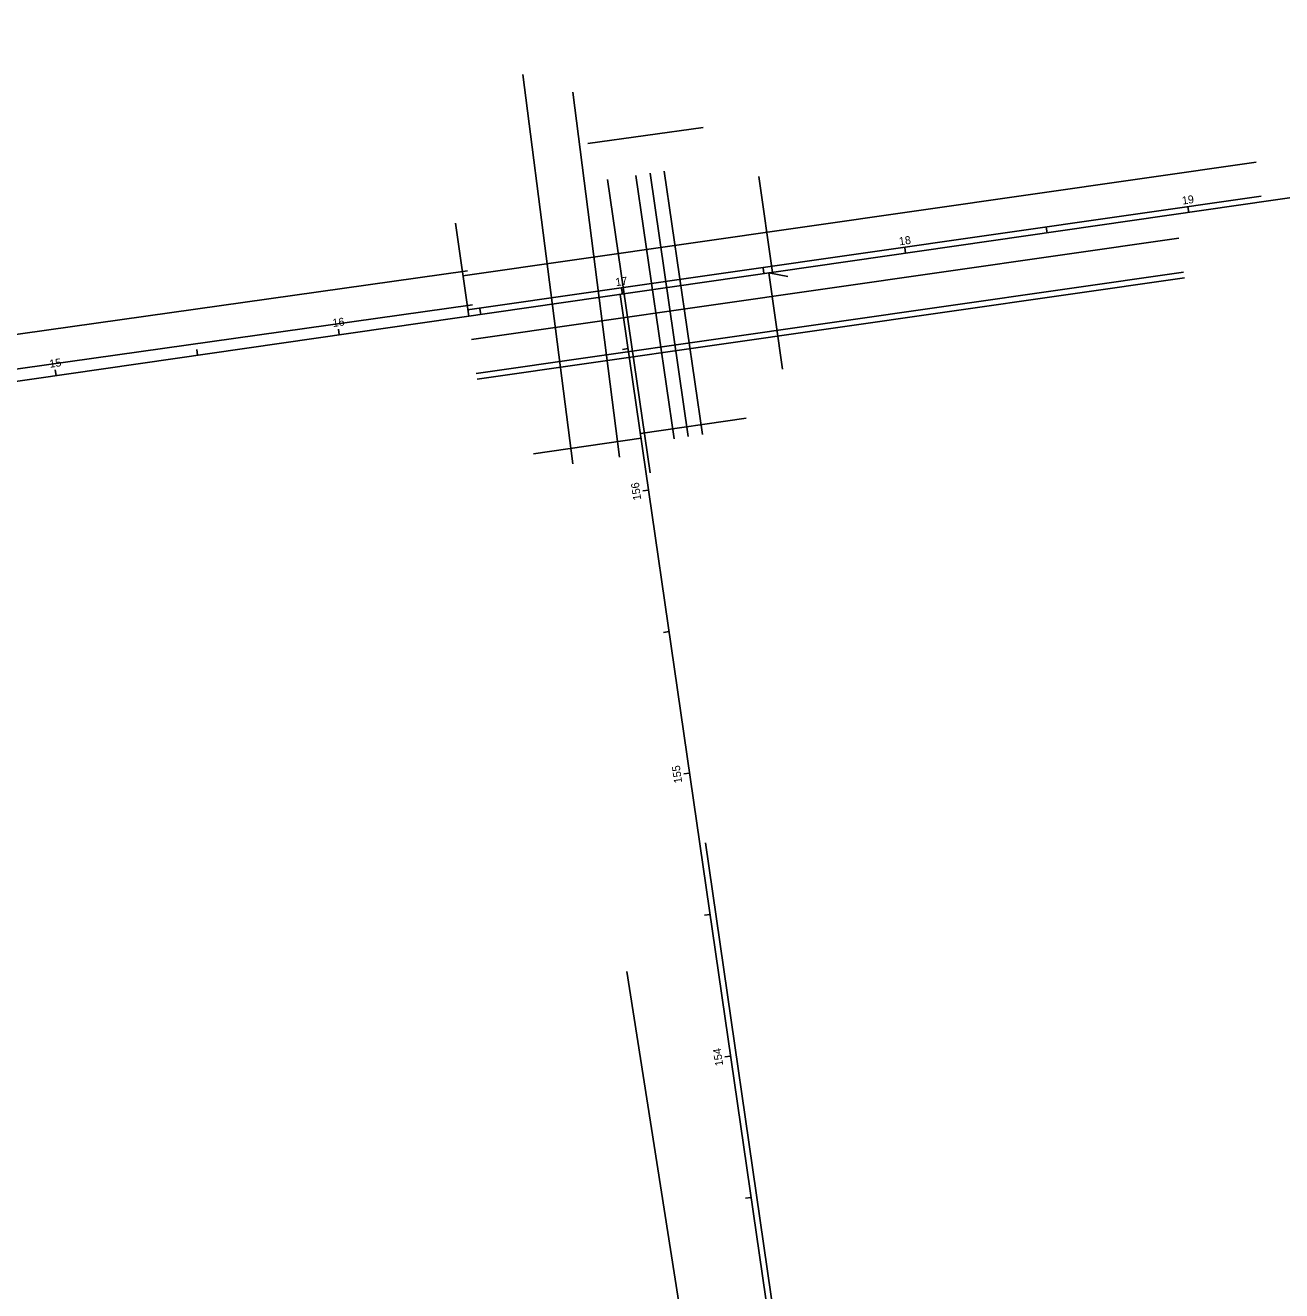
# Model space of a CAD drawing. Extents: x 1827063 to 1831280, y 711192 to 712800.
# Drawn here: x 1828341.4 to 1828780.5, y 712025.4 to 712468 of the extents above; entities that cross this region are included whole.
import ezdxf

# ---------------------------------------------------------------- set-up
doc = ezdxf.new("R2010")
doc.units = 0
for name, color, linetype in [('DR_P_Storm_Sewer', 7, 'Continuous'), ('PV_P_Walk', 7, 'Continuous'), ('UT_X_FO', 7, 'Continuous')]:
    doc.layers.add(name, color=color, linetype=linetype)

msp = doc.modelspace()

# ---------------------------------------------------------------- linework, layer by layer
at = {"layer": 'DR_P_Storm_Sewer'}
for p, q in [((1827917.05, 712282.69), (1829201.8, 712467.95)), ((1828748.02, 712402.52), (1828747.73, 712404.5)), ((1828698.53, 712395.38), (1828698.24, 712397.36)), ((1828649.04, 712388.24), (1828648.75, 712390.22)), ((1828599.55, 712381.11), (1828599.27, 712383.09)), ((1828577.13, 712181.7), (1828549.31, 712373.86)), ((1828550.06, 712373.97), (1828549.78, 712375.95)), ((1828500.58, 712366.84), (1828500.29, 712368.82)), ((1828451.09, 712359.7), (1828450.8, 712361.68)), ((1828401.6, 712352.56), (1828401.31, 712354.54)), ((1828552.06, 712354.9), (1828550.08, 712354.61)), ((1828352.11, 712345.43), (1828351.83, 712347.41)), ((1828559.22, 712305.41), (1828557.24, 712305.13)), ((1828566.39, 712255.93), (1828564.41, 712255.64)), ((1828573.55, 712206.45), (1828571.57, 712206.16)), ((1828611.13, 711946.89), (1828577.13, 712181.7)), ((1828580.71, 712156.96), (1828578.73, 712156.68)), ((1828587.88, 712107.48), (1828585.9, 712107.19)), ((1828595.04, 712057.99), (1828593.06, 712057.71))]:
    msp.add_line(p, q, dxfattribs=at)
at = {"layer": 'PV_P_Walk'}
for p, q in [((1828515.27, 712450.72), (1828532.73, 712314.63)), ((1828549.07, 712316.94), (1828532.69, 712444.62)), ((1828578.25, 712432.26), (1828537.95, 712426.67)), ((1828494.26, 712380.3), (1828771.63, 712420.12)), ((1828559.76, 712311.48), (1828544.9, 712413.98)), ((1828568.14, 712323.37), (1828554.79, 712415.48)), ((1828573.09, 712324.09), (1828559.73, 712416.2)), ((1828578.03, 712324.8), (1828564.68, 712416.92)), ((1828597.71, 712415.06), (1828602.54, 712381.54)), ((1828495.91, 712368.42), (1828773.33, 712408.24)), ((1828491.7, 712398.78), (1828496.39, 712366.23)), ((1828497.35, 712358.01), (1828744.54, 712393.5)), ((1828004.58, 712312.75), (1828495.96, 712382.05)), ((1828499, 712346.13), (1828746.25, 712381.62)), ((1828499.28, 712344.15), (1828746.53, 712379.64)), ((1828606.06, 712347.71), (1828601.21, 712381.35)), ((1828601.21, 712381.35), (1828607.91, 712380.11)), ((1828006.3, 712300.88), (1828497.63, 712370.16)), ((1828593.31, 712330.59), (1828556.35, 712325.24)), ((1828519, 712318.06), (1828556.6, 712323.51)), ((1828722.4, 711192.31), (1828579.11, 712181.99))]:
    msp.add_line(p, q, dxfattribs=at)
at = {"layer": 'UT_X_FO'}
msp.add_line((1828583.09, 711936.93), (1828551.66, 712137), dxfattribs=at)

# ---------------------------------------------------------------- texts
at = {"layer": 'DR_P_Storm_Sewer'}
for s, rotation, p in [('19', 8.2055, (1828745.89, 712405.24)), ('18', 8.2055, (1828646.95, 712390.98)), ('17', 8.2055, (1828547.86, 712376.69)), ('16', 8.2055, (1828448.94, 712362.42)), ('15', 8.2055, (1828349.97, 712348.15)), ('156', 98.238, (1828556.68, 712302.06)), ('155', 98.238, (1828571, 712203.1)), ('154', 98.238, (1828585.33, 712104.17))]:
    msp.add_text(s, height=2.8, rotation=rotation, dxfattribs=at).set_placement(p)

doc.saveas('drawing.dxf')
